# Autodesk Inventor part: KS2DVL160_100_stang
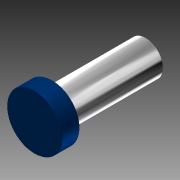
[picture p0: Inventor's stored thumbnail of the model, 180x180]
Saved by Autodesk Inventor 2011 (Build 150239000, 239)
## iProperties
Created: 2010-11
Document SubType Name: Modeling
Designer: TB
Mass: 161.233 g
Surface Area: 236.814 cm^2
Volume: 161.233 cm^3
Density: 1 g/cm^3
Author: TB
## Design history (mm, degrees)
sketch "Sketch2"
  geometry: L1 (-35, -3)-(-35, 3) reference; L2 (-35, -9)-(-35, 9) reference; L3 (-35, 50)-(-358, 50); L4 (-358, 50)-(-358, 0); L5 (-358, 0)-(-35, 0); L6 (-35, 0)-(-35, 50); L7 (-358, 50)-(-306, 50); L8 (-306, 50)-(-306, 80); L9 (-306, 80)-(-358, 80); L10 (-358, 80)-(-358, 50); 1 further point
  constraints: 16 end point, 4 parallel, 2 horizontal, 2 perpendicular, 1 midpoint
  dimensions: "Dia" = 100 diameter of L3 L5; "d3" = 323 distance of L3.start L3.end (computed from Slaglengde, Forlengelse_rør); "StempelDia" = 160 diameter of L9 L5; "StempelLengde" = 52 distance of L8.end L9.end
revolve "Revolution1" sketch "Sketch2" stored, may be unused: angle "d6" = 90 deg
fillet "Fillet1" dims "d7" = 2
sketch "Sketch3"
  geometry: L1 (-358, -78)-(-358, 78) reference; L2 (-358, 0)-(-358.01, 0); L3 (-358, 0)-(-358, 0.01); A1 r 0.01 centre (-358, 0) between (-358, 0.01) and (-358.01, 0); 1 further point
  constraints: 4 end point, 2 point on circle, 1 centre point, 1 midpoint, 1 perpendicular, 1 point on line
  dimensions: "d8" = 0.01 distance of L2.start L2.end; "d9" = 0.01 distance of L2.start L3.end (= d8); "d10" = 0.01 radius of A1 (= d8)
revolve "Revolution2" sketch "Sketch3" stored, may be unused: angle "d11" = 90 deg
body "Solid1"
node "Projected Loop2"
other parameters: "Forlengelse_rør" = 0
